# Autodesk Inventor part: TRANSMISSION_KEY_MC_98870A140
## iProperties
Created: 2008-11
Part Number: TRANSMISSION_KEY_MC_98870A140
Document SubType Name: Modeling
Designer: ETUDIANT
Author: ETUDIANT
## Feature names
1. Base1
